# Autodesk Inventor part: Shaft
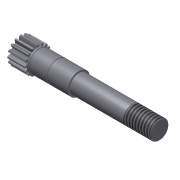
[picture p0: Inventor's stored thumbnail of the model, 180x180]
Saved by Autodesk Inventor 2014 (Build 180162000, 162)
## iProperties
Created: 2010-12
Part Number: Shaft
Material: Steel
Document SubType Name: Modeling
Designer: Thom Tremblay
Density: 1 g/cm^3
Appearance: Steel
CustomPartVersion: 0
Author: Thom Tremblay
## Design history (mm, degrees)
sketch "Main Sketch"
  geometry: L1 (0, 0)-(95, 0) reference; L2 (0, 0)-(0, 12.5); L3 (12, 12.5)-(12, 7.5); L4 (0, 12.5)-(12, 12.5); L5 (40, 7.5)-(40, 6.5); L6 (12, 7.5)-(40, 7.5); L7 (95, 6.5)-(95, 0); L8 (40, 6.5)-(95, 6.5)
  constraints: 16 end point, 4 vertical, 2 horizontal
  dimensions: "d3" = 25 diameter of L4 L1 (derived); "d5" = 15 diameter of L6 L1 (derived); "d13" = 13 diameter of L8 L1 (derived)
revolve "Revolution1" sketch "Main Sketch" stored, may be unused: angle "d6" = 0 deg
chamfer "Chamfer3" distance "d14" = 0.5; stored, may be unused: second distance "d15" = 0.125, angle "d16" = 45 deg
node "Retaining Ring Groove2"
node "Retaining Ring Groove1"
chamfer "Chamfer1" distance "d7" = 0.5; stored, may be unused: second distance "d8" = 0.125, angle "d9" = 45 deg
node "Spur Gear Teeth1"
thread "Thread1" dims "d17" = 18, "d18" = 0
body "Solid1"
feature "iFeature27:1"
feature "iFeature27:2"
feature "Spur Gear1"
other parameters: "d0" = 0, "d1" = 0, "d2" = 0
